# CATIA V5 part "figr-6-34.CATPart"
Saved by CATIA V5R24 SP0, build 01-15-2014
Part number: Part1
Bounding box of the stored display mesh (mm): x -40.3 to 40.3, y -45.975 to 45.975, z 0 to 40
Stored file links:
  D:\KAVITA\CATIA V5-6R2014 Project_ Kavita\CATIA V5-6R2014_partfiles\Partfiles\c06_catia_v5-6r2014_prt\figr-6-34.CATPart
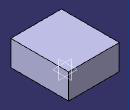
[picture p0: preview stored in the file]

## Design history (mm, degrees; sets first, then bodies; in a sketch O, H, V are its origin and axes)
Body1 (main body)
  Sketch1 on xy-plane, origin (0, 0, 0), H (1, 0, 0), V (0, 1, 0)
    line L1 (-40.2998, 45.9753) -> (40.2998, 45.9753)
    line L2 (40.2998, 45.9753) -> (40.2998, -45.9753)
    line L3 (40.2998, -45.9753) -> (-40.2998, -45.9753)
    line L4 (-40.2998, -45.9753) -> (-40.2998, 45.9753)
    axis line L5 (40.2998, -45.9753) -> (-40.2998, 45.9753)
    horizontal: L1 H, L3 H
    vertical: L2 V, L4 V
    midpoint: O L5
  Pad1: profile Sketch1, direction (0, 0, 1), length 40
